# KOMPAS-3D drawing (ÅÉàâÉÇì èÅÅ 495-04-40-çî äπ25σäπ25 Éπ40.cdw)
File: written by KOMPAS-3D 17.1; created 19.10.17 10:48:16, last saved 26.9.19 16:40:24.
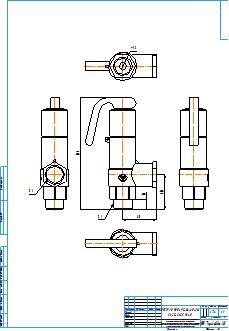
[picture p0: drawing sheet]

Sheet 1: A2, portrait

Title block, sheet 1: name: ПРЕГРАН КПП 495-04-40-ЗМ / Ду25хДу25 Ру40; material: Сталь 20  ГОСТ 1050-2013; mass: 1,74; sheets: 1; sheet format: A2; stored path: C:\Users\kka\KOMPAS_Work\!Trash\Прегран КПП 495\ПРЕГРАН КПП 495-04-40-ЗМ\KOMPAS 2D\Прегран КПП 495 Ду25хДу25 Ру40.cdw

Views: Спереди 6, Проекционный вид 7, Проекционный вид 8, Проекционный вид 9, Проекционный вид 10
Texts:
  kka
  adl
  Рама для чертежей
  Лит-Масса-Масштаб
  Материал-Предприятие
  Масштаб
  Изм.
  Лист
  № докум.
  Подп.
  Дата
  Лит.
  Разраб.
  Пров.
  Т.контр.
  Листов
  Внимание! Данный продукт является объектом авторского права ООО «Торговый Дом АДЛ».
  Запрещается изменение, копирование, распространение
  (в том числе путем копирования на другие сайты и ресурсы в Интернете)
  или любое иное использование информации и объектов без предварительного
  согласия правообладателя (ООО «Торговый Дом АДЛ»).
  Н.контр.
  Утв.
  ООО "Торговый дом АДЛ"
  Изменение
  Номер документа
  Подпись
  Обозначение документа
  Наименование изделия
  Масса изделия по ГОСТ 2.109-73
  Порядковый номер листа
  Общее количество листов в документе
  Характер работы, выполненной лицом, подписавшим документ
  Наименование или индекс предприятия, выпускающего документ
  Инв. № подл.
  Подп. и дата
  Взам. инв. №
  Инв. № дубл.
  Инвентарный номер подлинника по ГОСТ 2.501-68
  Подпись принявшего подлинник в отдел технической документации
  Инвентарный номер подлинника, взамен которого выпущен данный подлинник
  Инвентарный номер дубликата по ГОСТ 2.502-68
  Подпись принявшего дубликат в отдел технической документации
  Справ. №
  Перв. примен.
  Обозначение документа, взамен или на основании которого выпущен данный документ
  Обозначение документа, в котором впервые записан данный документ
  Подпись лица, копировавшего чертеж
  Обозначение формата листа
  !Рама для чертежа
Dimensions and other numbers on the sheet: 61,5; 18; 60; 199; 13; 1,74; 1:1; 1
